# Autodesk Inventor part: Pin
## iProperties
Shininess: 41.0
Length Units: 11272
Angle Units: 11279
Time Units: 11290
Mass Units: 11286
Length Display Precision: 4
Angle Display Precision: 2
Compacted: True
Manager: Lebovitz
Company: Autodesk
Created: 2000-11
Part Number: Pin
Document SubType Name: Modeling
Designer: The PD Team
Project: Inventor Samples
Density: 0.0
Volumn: 0.0
Area: 0.0
PropertySet Name: Model Information
Control State: 0
Master: False
Checked Out: False
Author: The PD Team
Revision Number: A
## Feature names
1. Extrusion1
